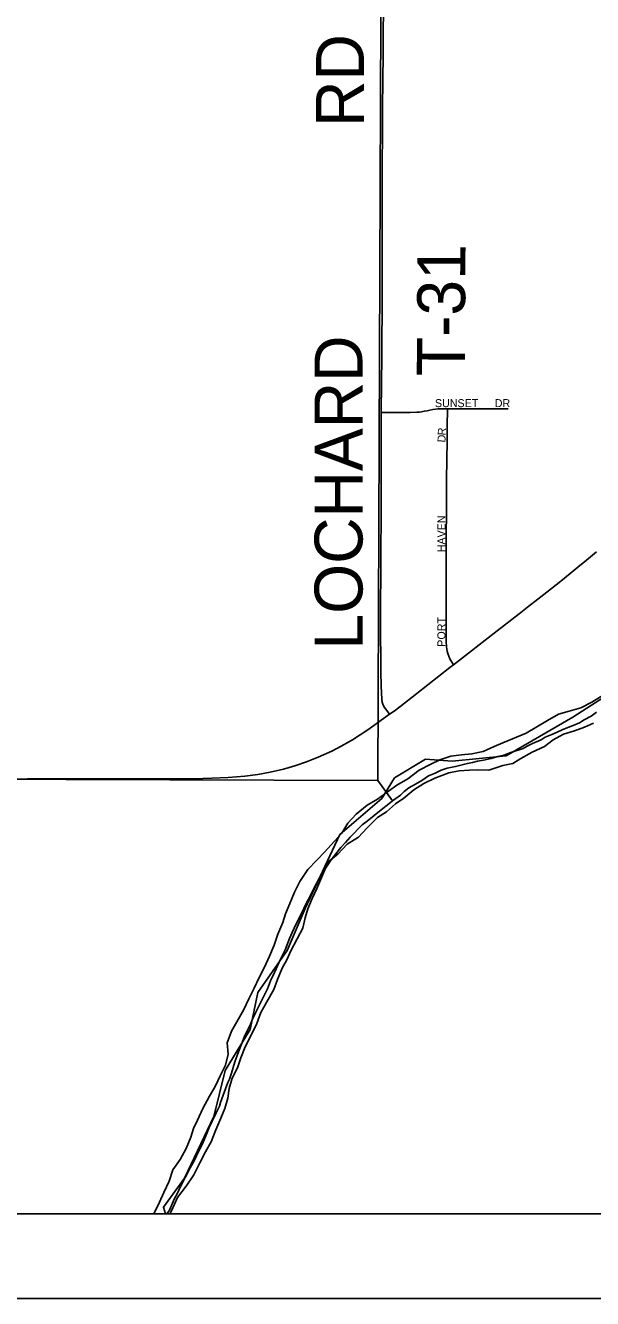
# Model space of a CAD drawing. Extents: x -784 to 1375, y -225 to 440.
# Drawn here: x 550.75 to 564.18, y 281.31 to 311.43 of the extents above; entities that cross this region are included whole.
import ezdxf

# ---------------------------------------------------------------- set-up
doc = ezdxf.new("R2010")
doc.units = 0
for name, color, linetype in [('GM_X_Major_River', 7, 'Continuous'), ('GM_X_Section', 7, 'Continuous'), ('GM_X_State_Route', 7, 'Continuous'), ('GM_X_Township', 7, 'Continuous'), ('GM_X_Township_Road', 7, 'Continuous'), ('GM_X_Township_Road_Text', 7, 'Continuous'), ('GM_X_Township_Subdivision', 7, 'Continuous'), ('GM_X_Township_Subdivision_Text', 7, 'Continuous'), ('SH_Data', 7, 'Continuous')]:
    doc.layers.add(name, color=color, linetype=linetype)

msp = doc.modelspace()

# ---------------------------------------------------------------- linework, layer by layer
at = {"layer": 'GM_X_Major_River'}
for points in [[(564.412, 295.571), (564.165, 295.418), (563.903, 295.287), (563.627, 295.21), (563.374, 295.133), (563.119, 294.987), (562.864, 294.833), (562.61, 294.687), (562.056, 294.457), (561.856, 294.371), (561.595, 294.256), (561.327, 294.194), (561.083, 294.177), (560.823, 294.138), (560.563, 294.053), (560.355, 293.952), (560.077, 293.814), (559.806, 293.607), (559.551, 293.454), (559.35, 293.314), (559.094, 293.122), (558.847, 292.984), (558.583, 292.769), (558.388, 292.553), (558.245, 292.32), (558.073, 292.127), (557.838, 291.873), (557.651, 291.68), (557.44, 291.457), (557.25, 291.179), (557.122, 290.923), (557.017, 290.659), (556.912, 290.41), (556.846, 290.206), (556.733, 289.927), (556.643, 289.67), (556.53, 289.406), (556.417, 289.15), (556.289, 288.901), (556.169, 288.653), (556.041, 288.404), (555.92, 288.133), (555.634, 287.637), (555.529, 287.358), (555.553, 287.09), (555.493, 286.833), (555.373, 286.592), (555.245, 286.328), (555.11, 286.095), (554.951, 285.809), (554.83, 285.53), (554.734, 285.335), (554.667, 285.123), (554.562, 284.859), (554.419, 284.595), (554.245, 284.356), (554.155, 284.084), (554.027, 283.82), (553.93, 283.586), (553.81, 283.345), (553.789, 283.309)], [(554.171, 283.309), (554.214, 283.381), (554.351, 283.698), (554.555, 283.967), (554.737, 284.237), (554.881, 284.523), (555.017, 284.779), (555.152, 285.019), (555.265, 285.298), (555.379, 285.578), (555.475, 285.804), (555.542, 286.046), (555.578, 286.282), (555.645, 286.524), (555.773, 286.765), (555.855, 287.006), (555.96, 287.263), (556.08, 287.512), (556.232, 287.813), (556.33, 288.077), (556.466, 288.333), (556.632, 288.618), (556.722, 288.86), (556.835, 289.124), (556.946, 289.319), (557.035, 289.538), (557.187, 289.816), (557.322, 290.072), (557.381, 290.315), (557.44, 290.527), (557.545, 290.775), (557.657, 291.009), (557.819, 291.401), (557.924, 291.643), (558.149, 291.827), (558.375, 292.058), (558.638, 292.227), (558.841, 292.435), (559.091, 292.688), (559.3, 292.827), (559.517, 293.012), (559.711, 293.145), (559.952, 293.344), (560.191, 293.498), (560.445, 293.622), (560.776, 293.75), (561.028, 293.797), (561.272, 293.807), (561.47, 293.817), (561.728, 293.81), (562.058, 293.924), (562.295, 293.971), (562.488, 294.088), (562.751, 294.234), (563.043, 294.372), (563.253, 294.526), (563.499, 294.665), (563.752, 294.742), (563.99, 294.828), (564.206, 294.921)]]:
    msp.add_lwpolyline(points, dxfattribs=at)
at = {"layer": 'GM_X_Section'}
for p, q in [((539.3, 283.309), (554.103, 283.309)), ((554.103, 283.309), (564.388, 283.309))]:
    msp.add_line(p, q, dxfattribs=at)
msp.add_lwpolyline([(539.515, 313.692), (559.175, 313.642), (559.1, 293.569), (539.382, 293.628)], close=True, dxfattribs=at)
for points in [[(564.279, 295.184), (564.149, 295.088), (563.988, 295), (563.873, 294.933), (563.721, 294.868), (563.599, 294.817), (563.461, 294.766), (563.347, 294.708), (563.217, 294.657), (563.064, 294.592), (562.965, 294.525), (562.759, 294.438), (562.637, 294.379), (562.537, 294.32), (562.248, 294.227), (562.08, 294.169), (561.943, 294.134), (561.783, 294.083), (561.601, 294.049), (561.456, 294.021), (561.342, 293.993), (561.221, 293.972), (560.939, 293.901), (560.741, 293.859), (560.597, 293.809), (560.452, 293.743), (560.299, 293.677), (560.138, 293.567), (559.992, 293.478), (559.832, 293.39), (559.724, 293.309), (559.632, 293.219), (559.448, 293.086), (559.1, 293.569), (559.175, 313.642)], [(564.279, 295.184), (564.149, 295.088), (563.988, 295), (563.873, 294.933), (563.721, 294.868), (563.599, 294.817), (563.461, 294.766), (563.347, 294.708), (563.217, 294.657), (563.064, 294.592), (562.965, 294.525), (562.759, 294.438), (562.637, 294.379), (562.537, 294.32), (562.248, 294.227), (562.08, 294.169), (561.943, 294.134), (561.783, 294.083), (561.601, 294.049), (561.456, 294.021), (561.342, 293.993), (561.221, 293.972), (560.939, 293.901), (560.741, 293.859), (560.597, 293.809), (560.452, 293.743), (560.299, 293.677), (560.138, 293.567), (559.992, 293.478), (559.832, 293.39), (559.724, 293.309), (559.632, 293.219), (559.448, 293.086), (559.356, 293.012), (559.179, 292.871), (559.01, 292.738), (558.849, 292.604), (558.726, 292.515), (558.649, 292.441), (558.518, 292.307), (558.441, 292.225), (558.332, 292.098), (558.224, 291.979), (558.1, 291.829), (557.992, 291.687), (557.899, 291.545), (557.798, 291.395), (557.72, 291.26), (557.586, 291.013), (557.5, 290.847), (557.406, 290.675), (557.273, 290.389), (557.163, 290.172), (557.068, 289.969), (557.005, 289.826), (556.902, 289.563), (556.8, 289.352), (556.651, 289.022), (556.556, 288.826), (556.485, 288.638), (556.406, 288.48), (556.312, 288.293), (556.202, 288.067), (556.131, 287.917), (556.084, 287.804), (555.935, 287.496), (555.871, 287.331), (555.8, 287.143), (555.713, 286.909), (555.632, 286.638), (555.584, 286.502), (555.545, 286.42), (555.434, 286.119), (555.37, 285.946), (555.346, 285.863), (555.267, 285.705), (555.173, 285.502), (555.102, 285.352), (555.039, 285.201), (554.944, 284.968), (554.803, 284.683), (554.748, 284.563), (554.654, 284.398), (554.536, 284.172), (554.45, 284.007), (554.387, 283.872), (554.34, 283.767), (554.286, 283.677), (554.167, 283.398), (554.103, 283.309)], [(554.103, 283.309), (554.167, 283.398), (554.286, 283.677), (554.34, 283.767), (554.387, 283.872), (554.45, 284.007), (554.536, 284.172), (554.654, 284.398), (554.748, 284.563), (554.803, 284.683), (554.944, 284.968), (555.039, 285.201), (555.102, 285.352), (555.173, 285.502), (555.267, 285.705), (555.346, 285.863), (555.37, 285.946), (555.434, 286.119), (555.545, 286.42), (555.584, 286.502), (555.632, 286.638), (555.713, 286.909), (555.8, 287.143), (555.871, 287.331), (555.935, 287.496), (556.084, 287.804), (556.131, 287.917), (556.202, 288.067), (556.312, 288.293), (556.406, 288.48), (556.485, 288.638), (556.556, 288.826), (556.651, 289.022), (556.8, 289.352), (556.902, 289.563), (557.005, 289.826), (557.068, 289.969), (557.163, 290.172), (557.273, 290.389), (557.406, 290.675), (557.5, 290.847), (557.586, 291.013), (557.72, 291.26), (557.798, 291.395), (557.899, 291.545), (557.992, 291.687), (558.1, 291.829), (558.224, 291.979), (558.332, 292.098), (558.441, 292.225), (558.518, 292.307), (558.649, 292.441), (558.726, 292.515), (558.849, 292.604), (559.01, 292.738), (559.179, 292.871), (559.356, 293.012), (559.448, 293.086), (559.1, 293.569), (539.382, 293.628)]]:
    msp.add_lwpolyline(points, dxfattribs=at)
at = {"layer": 'GM_X_State_Route'}
for points in [[(563.991, 298.739), (564.277, 298.976)], [(549.823, 293.599), (550.805, 293.602), (551.203, 293.605), (552.198, 293.605), (553.926, 293.602), (554.286, 293.603), (554.952, 293.615), (555.168, 293.619), (555.552, 293.636), (555.948, 293.669), (556.255, 293.71), (556.547, 293.764), (556.861, 293.837), (557.136, 293.914), (557.405, 294.006), (557.682, 294.116), (558.006, 294.262), (558.23, 294.376), (558.498, 294.531), (558.865, 294.763), (559.375, 295.132), (559.481, 295.21), (559.621, 295.313), (560.025, 295.623), (560.807, 296.236), (560.891, 296.303), (561.924, 297.106), (562.444, 297.511), (562.639, 297.664), (562.885, 297.854), (563.101, 298.021), (563.432, 298.283), (563.923, 298.683), (563.991, 298.739)]]:
    msp.add_lwpolyline(points, dxfattribs=at)
at = {"layer": 'GM_X_Township'}
for points in [[(554.071, 283.309), (580.236, 283.309), (580.236, 307.641)], [(539.084, 283.309), (554.071, 283.309), (554.022, 283.47), (554.516, 284.159), (555.212, 285.618), (555.48, 286.707), (556.071, 287.674), (556.254, 288.552), (556.952, 289.545), (557.376, 290.535), (558.199, 292.286), (559.194, 293.144), (559.49, 293.627), (560.224, 294.069), (560.86, 294.026), (562.134, 294.146), (563.718, 295.062), (564.688, 295.684)], [(564.688, 295.684), (563.718, 295.062), (562.134, 294.146), (560.86, 294.026), (560.224, 294.069), (559.49, 293.627), (559.194, 293.144), (558.199, 292.286), (557.376, 290.535), (556.952, 289.545), (556.254, 288.552), (556.071, 287.674), (555.48, 286.707), (555.212, 285.618), (554.516, 284.159), (554.022, 283.47), (554.071, 283.309)]]:
    msp.add_lwpolyline(points, dxfattribs=at)
at = {"layer": 'GM_X_Township_Road'}
for points in [[(559.18, 302.27), (559.188, 302.974), (559.191, 303.583), (559.193, 303.993), (559.2, 304.664), (559.202, 305.148), (559.202, 305.782), (559.198, 306.577), (559.2, 307.297), (559.201, 308.13), (559.207, 308.875), (559.209, 309.422), (559.217, 310.192), (559.222, 310.689), (559.223, 310.95), (559.228, 311.335), (559.232, 311.708), (559.238, 312.254), (559.24, 312.702), (559.25, 313.547), (559.251, 313.65)], [(559.375, 295.132), (559.238, 295.321), (559.216, 295.369), (559.203, 295.419), (559.192, 295.494), (559.181, 295.644), (559.174, 295.806), (559.17, 296.129), (559.167, 296.477), (559.163, 297.011), (559.163, 297.657), (559.166, 298.527), (559.168, 298.809), (559.174, 299.992), (559.177, 300.75), (559.178, 301.259), (559.178, 302.042), (559.18, 302.27)]]:
    msp.add_lwpolyline(points, dxfattribs=at)
at = {"layer": 'GM_X_Township_Subdivision'}
for points in [[(559.18, 302.27), (559.248, 302.27), (559.863, 302.275), (560.021, 302.279), (560.085, 302.284), (560.133, 302.291), (560.197, 302.302), (560.264, 302.315), (560.332, 302.33), (560.401, 302.343), (560.465, 302.353), (560.522, 302.36), (560.575, 302.361), (560.748, 302.362)], [(560.728, 300.676), (560.728, 300.69), (560.738, 301.61), (560.743, 301.945), (560.748, 302.362)], [(560.748, 302.362), (560.975, 302.363), (561.642, 302.361), (562.186, 302.362)], [(560.891, 296.303), (560.807, 296.448), (560.779, 296.505), (560.756, 296.573), (560.743, 296.627), (560.734, 296.676), (560.726, 296.739), (560.72, 296.849), (560.714, 297.087), (560.715, 297.485), (560.719, 297.882), (560.715, 298.566), (560.715, 298.864), (560.717, 299.212), (560.719, 299.361), (560.723, 299.896), (560.725, 300.169), (560.726, 300.454), (560.728, 300.676)]]:
    msp.add_lwpolyline(points, dxfattribs=at)
at = {"layer": 'SH_Data'}
for p, q in [((444.236, 283.309), (580.236, 283.309)), ((442.236, 281.309), (581.184, 281.309))]:
    msp.add_line(p, q, dxfattribs=at)

# ---------------------------------------------------------------- texts
at = {"layer": 'GM_X_Township_Road_Text'}
for s, rotation, p in [('RD', 90, (558.77, 309.031)), ('T-31', 89.6471, (561.156, 303.129)), ('LOCHARD', 90, (558.736, 296.665))]:
    msp.add_text(s, height=1.1364, rotation=rotation, dxfattribs=at).set_placement(p)
at = {"layer": 'GM_X_Township_Subdivision_Text'}
for s, height, rotation, p in [('SUNSET', 0.1894, 0, (560.45, 302.4)), ('DR', 0.1894, 0, (561.867, 302.4)), ('R', 0.189, 86.6949, (560.704, 301.728)), ('D', 0.189, 87.6386, (560.698, 301.563)), ('HAVEN', 0.1894, 90, (560.698, 298.965)), ('PORT', 0.1894, 90, (560.698, 296.731))]:
    msp.add_text(s, height=height, rotation=rotation, dxfattribs=at).set_placement(p)

doc.saveas('drawing.dxf')
